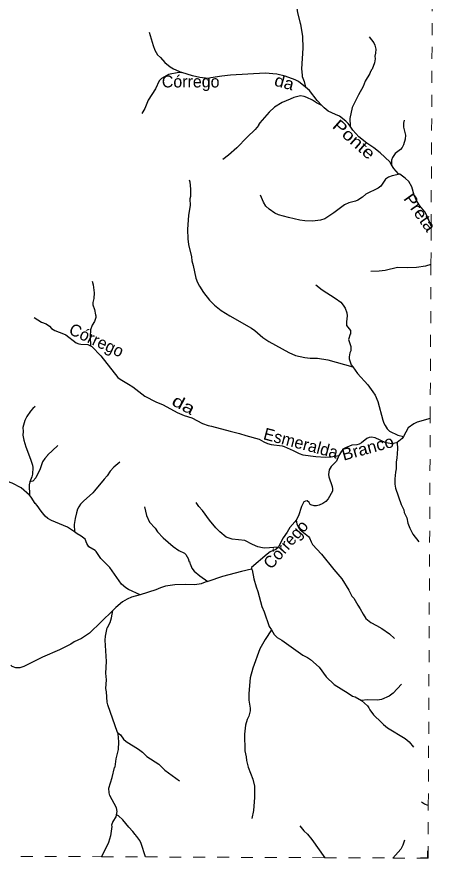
# Model space of a CAD drawing. Extents: x 551.6 to 577.6, y 7567 to 7594.7.
# Drawn here: x 573.98 to 577.56, y 7566.95 to 7573.99 of the extents above; entities that cross this region are included whole.
import ezdxf
from ezdxf.enums import TextEntityAlignment as Align

# ---------------------------------------------------------------- set-up
doc = ezdxf.new("R2010")
doc.units = 0
doc.header["$LTSCALE"] = 0.04
doc.linetypes.add('SHORT_DASHED', pattern=[2.7, 1.5, -1.2])
for name, color, linetype, lineweight in [('53', 7, 'SHORT_DASHED', 13), ('63', 7, 'Continuous', 25), ('7', 7, 'Continuous', 25)]:
    doc.layers.add(name, color=color, linetype=linetype, lineweight=lineweight)
doc.layers.add('61', color=7, linetype='Continuous')

msp = doc.modelspace()

# ---------------------------------------------------------------- linework, layer by layer
at = {"layer": '53'}
for points in [[(577.4204, 7566.9518), (577.4226, 7567.3928), (577.4384, 7570.6314), (577.4446, 7571.9213), (577.4462, 7572.242), (577.4659, 7576.2813), (577.4696, 7577.0412), (577.4755, 7578.252), (577.4832, 7579.8317), (577.4989, 7583.0336), (577.5065, 7584.6034), (577.518, 7586.9644), (577.5184, 7587.0352), (577.519, 7587.1599), (577.5202, 7587.417), (577.5286, 7589.1281), (577.5292, 7589.2596), (577.5446, 7592.4063), (577.549, 7593.3187), (577.5554, 7594.6251)], [(551.613, 7567.0572), (552.9162, 7567.0524), (553.7221, 7567.0495), (554.9107, 7567.0451), (556.1477, 7567.0406), (557.2075, 7567.0367), (559.4055, 7567.0287), (559.6981, 7567.0276), (560.556, 7567.0244), (562.9715, 7567.0156), (564.6334, 7567.0092), (566.4358, 7567.0011), (566.7714, 7566.9996), (570.8595, 7566.9812), (572.5416, 7566.9737), (572.8363, 7566.9724), (573.5039, 7566.9694), (573.609, 7566.9689), (574.6855, 7566.9641), (575.0536, 7566.9624), (576.5544, 7566.9557), (577.1266, 7566.9531), (577.4204, 7566.9518)]]:
    msp.add_lwpolyline(points, dxfattribs=at)
at = {"layer": '63'}
msp.add_lwpolyline([(577.3571, 7566.9538), (577.4187, 7566.9538), (577.4187, 7567.0145)], dxfattribs=at)
at = {"layer": '7'}
for points in [[(576.3305, 7574.5183), (576.3425, 7574.4627), (576.3441, 7574.4289), (576.3361, 7574.3388), (576.3208, 7574.2648), (576.3159, 7574.1344), (576.3208, 7574.0668), (576.3272, 7574.0265), (576.3489, 7573.9404), (576.353, 7573.9331), (576.3691, 7573.8302), (576.3723, 7573.732), (576.3594, 7573.5598), (576.365, 7573.505)], [(575.083, 7573.8664), (575.1168, 7573.7529), (575.1329, 7573.7143), (575.1554, 7573.6748), (575.1804, 7573.6539), (575.2142, 7573.6121), (575.2601, 7573.5758), (575.289, 7573.5581), (575.3583, 7573.5283)], [(576.926, 7573.8278), (576.9654, 7573.7771), (576.9743, 7573.7577), (576.9831, 7573.7231), (576.9807, 7573.6901), (576.9751, 7573.6644), (576.9767, 7573.6418), (576.9727, 7573.608), (576.9517, 7573.5573), (576.9437, 7573.5485), (576.9437, 7573.5429), (576.9373, 7573.5356), (576.9332, 7573.5211), (576.8938, 7573.4551), (576.8761, 7573.4101), (576.8366, 7573.3425), (576.7835, 7573.2346), (576.765, 7573.1445), (576.7674, 7573.0787)], [(575.3583, 7573.5283), (575.3333, 7573.5275), (575.2456, 7573.5115), (575.1868, 7573.4785), (575.1683, 7573.4584), (575.1377, 7573.3908), (575.0749, 7573.2958), (575.0476, 7573.2266), (575.0226, 7573.1855)], [(575.5997, 7573.4841), (575.5772, 7573.4793), (575.5079, 7573.4873), (575.4484, 7573.5002), (575.3583, 7573.5283)], [(576.394, 7573.4063), (576.3353, 7573.4519), (576.3063, 7573.4656), (576.2226, 7573.497), (576.155, 7573.5147), (576.0552, 7573.5227), (575.7655, 7573.505), (575.693, 7573.4986), (575.5997, 7573.4841)], [(576.365, 7573.505), (576.3666, 7573.4938), (576.3827, 7573.4535), (576.394, 7573.4063)], [(576.5304, 7573.2525), (576.4914, 7573.2926), (576.4262, 7573.3787), (576.394, 7573.4063)], [(576.5304, 7573.2525), (576.485, 7573.274), (576.4512, 7573.2966), (576.4061, 7573.3191), (576.3836, 7573.3272), (576.3514, 7573.3328), (576.295, 7573.3191), (576.2645, 7573.3038), (576.1969, 7573.2773), (576.1349, 7573.2386), (576.089, 7573.196), (576.0101, 7573.1059), (575.9988, 7573.0905), (575.9988, 7573.0857), (575.9715, 7573.0519), (575.9055, 7572.9883), (575.8178, 7572.8966), (575.7486, 7572.8362), (575.7003, 7572.7992)], [(576.6443, 7573.1767), (576.5848, 7573.2056), (576.5501, 7573.2322), (576.5304, 7573.2525)], [(576.7674, 7573.0787), (576.7522, 7573.101), (576.7328, 7573.1195), (576.6781, 7573.1614), (576.6443, 7573.1767)], [(577.2206, 7573.1292), (577.2141, 7573.1042), (577.2141, 7573.0704), (577.2302, 7573.0028), (577.2286, 7572.9706), (577.2141, 7572.9224), (577.204, 7572.901), (577.1884, 7572.8837), (577.1457, 7572.8499), (577.1224, 7572.8177), (577.1127, 7572.7936), (577.1135, 7572.7567)], [(577.1135, 7572.7567), (577.1014, 7572.7807), (577.0193, 7572.8547), (576.967, 7572.8974), (576.9075, 7572.9368), (576.8391, 7572.9884), (576.79, 7573.0455), (576.7674, 7573.0787)], [(577.1831, 7572.6774), (577.1739, 7572.6809), (577.1344, 7572.7244), (577.1135, 7572.7567)], [(577.1831, 7572.6774), (577.1192, 7572.6632), (577.0902, 7572.6535), (577.0652, 7572.635), (577.0234, 7572.5771), (577.0017, 7572.561), (576.9002, 7572.5095), (576.8721, 7572.4853), (576.8326, 7572.4588), (576.8133, 7572.4507), (576.7554, 7572.4362), (576.72, 7572.4218), (576.6306, 7572.3542), (576.5566, 7572.3043), (576.5188, 7572.293), (576.4528, 7572.2833), (576.3884, 7572.2874)], [(577.4462, 7572.242), (577.4225, 7572.3075), (577.404, 7572.3429), (577.3928, 7572.3622), (577.3525, 7572.4121), (577.3244, 7572.4572), (577.3042, 7572.5023), (577.2849, 7572.5699), (577.2584, 7572.6165), (577.2294, 7572.6447), (577.1831, 7572.6774)], [(575.4194, 7572.6286), (575.4242, 7572.6117), (575.4291, 7572.5505), (575.4291, 7572.491), (575.4258, 7572.4717), (575.4274, 7572.4153), (575.4138, 7572.3332), (575.4065, 7572.2141), (575.4081, 7572.1369), (575.4146, 7572.0886), (575.4379, 7571.984), (575.4419, 7571.9518), (575.4532, 7571.9131), (575.4765, 7571.8069), (575.4894, 7571.7699), (575.5047, 7571.7401)], [(576.3884, 7572.2874), (576.3465, 7572.293), (576.25, 7572.3139), (576.1679, 7572.3381), (576.1357, 7572.3517), (576.0882, 7572.3847), (576.0624, 7572.4105), (576.0407, 7572.4427), (576.0166, 7572.5014)], [(577.4446, 7571.9213), (577.3992, 7571.9067), (577.3236, 7571.8954), (577.2479, 7571.8922), (577.1642, 7571.897), (577.0612, 7571.8705), (577.0097, 7571.864), (576.9397, 7571.8616)], [(574.6074, 7571.7803), (574.6162, 7571.7506), (574.6226, 7571.683), (574.6194, 7571.6379), (574.6122, 7571.6041), (574.6122, 7571.5848), (574.6275, 7571.5445), (574.6339, 7571.4995), (574.6387, 7571.4922), (574.6387, 7571.4777), (574.6251, 7571.4431), (574.6065, 7571.4142), (574.5929, 7571.3755), (574.5888, 7571.3195), (574.5922, 7571.2414)], [(575.5047, 7571.7401), (575.5393, 7571.6862), (575.59, 7571.6226), (575.6319, 7571.5799), (575.6866, 7571.5373), (575.759, 7571.4914), (575.9417, 7571.3884), (575.9707, 7571.3675), (576.0367, 7571.3087), (576.0858, 7571.2757), (576.2532, 7571.1848), (576.3111, 7571.1606), (576.3498, 7571.1518)], [(576.4793, 7571.7514), (576.5333, 7571.7079), (576.6427, 7571.6395), (576.6886, 7571.6049), (576.7103, 7571.5816), (576.7248, 7571.5558), (576.7393, 7571.5172), (576.7441, 7571.4914), (576.7361, 7571.4399), (576.7361, 7571.4093), (576.7699, 7571.3691), (576.7699, 7571.3385), (576.7666, 7571.3369), (576.7538, 7571.2934), (576.7747, 7571.2355), (576.7747, 7571.1985), (576.7658, 7571.1808), (576.7618, 7571.1647), (576.7586, 7571.1486), (576.7602, 7571.1309), (576.7763, 7571.081), (576.79, 7571.0632)], [(574.1197, 7571.4761), (574.1832, 7571.4375), (574.2219, 7571.4238), (574.2492, 7571.4045), (574.2669, 7571.3852), (574.2927, 7571.3675), (574.3667, 7571.3417), (574.3861, 7571.332), (574.4738, 7571.2645), (574.4939, 7571.2564), (574.5132, 7571.2532), (574.5712, 7571.2516), (574.5922, 7571.2414)], [(574.5922, 7571.2414), (574.6041, 7571.2355), (574.6798, 7571.1558), (574.8222, 7570.9763), (574.8416, 7570.961), (574.9108, 7570.9184)], [(576.3498, 7571.1518), (576.3884, 7571.1421), (576.4335, 7571.1373), (576.493, 7571.1357), (576.5799, 7571.1228), (576.79, 7571.0632)], [(576.79, 7571.0632), (576.8294, 7571.0101), (576.9163, 7570.9152), (576.959, 7570.8556), (576.9759, 7570.8267), (577.0008, 7570.7752), (577.0427, 7570.619)], [(574.9108, 7570.9184), (574.9462, 7570.8959), (575.0484, 7570.8202), (575.1393, 7570.7727), (575.2021, 7570.747), (575.318, 7570.6826), (575.376, 7570.6576), (575.442, 7570.6383), (575.5305, 7570.5916), (575.5788, 7570.5723), (575.6077, 7570.5675), (575.7639, 7570.5273)], [(574.1301, 7570.7325), (574.1108, 7570.7164), (574.0915, 7570.6947), (574.0609, 7570.6496), (574.0432, 7570.6158), (574.0255, 7570.5562), (574.0287, 7570.5224), (574.0271, 7570.4919), (574.0335, 7570.45), (574.0512, 7570.3937), (574.0915, 7570.2923), (574.1076, 7570.2408), (574.1108, 7570.2214), (574.106, 7570.1651), (574.1011, 7570.1426), (574.0845, 7570.1017)], [(577.0427, 7570.619), (577.0507, 7570.5933), (577.0612, 7570.5723), (577.0789, 7570.545), (577.0966, 7570.5273), (577.1658, 7570.4918), (577.2141, 7570.4812)], [(577.4384, 7570.6314), (577.33, 7570.6013), (577.301, 7570.5876), (577.2544, 7570.553), (577.2141, 7570.4812)], [(575.7639, 7570.5273), (575.8411, 7570.5079), (575.8942, 7570.4902), (576.0053, 7570.4597), (576.0447, 7570.4355), (576.0761, 7570.4218), (576.1051, 7570.4146), (576.1985, 7570.4033), (576.2146, 7570.3985), (576.2902, 7570.3655), (576.3393, 7570.3389), (576.3707, 7570.3293), (576.4801, 7570.3148), (576.5622, 7570.3083), (576.6073, 7570.31), (576.6736, 7570.3213)], [(577.1626, 7570.4325), (577.1546, 7570.4274), (577.1159, 7570.4202), (577.087, 7570.4242), (577.0676, 7570.4291), (576.9759, 7570.4693), (576.9469, 7570.4749), (576.9276, 7570.4725), (576.9083, 7570.4653), (576.8616, 7570.4275), (576.8423, 7570.417), (576.823, 7570.4114), (576.7827, 7570.4098), (576.7296, 7570.3872), (576.7127, 7570.3768), (576.6942, 7570.3599), (576.6781, 7570.3309), (576.6736, 7570.3213)], [(577.1626, 7570.4325), (577.1634, 7570.3792), (577.1578, 7570.3003), (577.1521, 7570.2697), (577.1529, 7570.2118), (577.1465, 7570.1828), (577.1417, 7570.1281), (577.1425, 7570.083), (577.1481, 7570.0492), (577.1956, 7569.9124), (577.2165, 7569.8673), (577.2213, 7569.8448), (577.2415, 7569.7997), (577.2511, 7569.7547), (577.2672, 7569.7128), (577.2938, 7569.6645), (577.3437, 7569.6009)], [(577.2141, 7570.4812), (577.2028, 7570.4645), (577.1626, 7570.4325)], [(574.3193, 7570.4074), (574.2315, 7570.3245), (574.2315, 7570.3212), (574.2098, 7570.2971), (574.1905, 7570.2681), (574.172, 7570.2102), (574.1341, 7570.1353), (574.1084, 7570.1088), (574.0845, 7570.1017)], [(576.6736, 7570.3213), (576.6524, 7570.2754), (576.6097, 7570.2311), (576.5912, 7570.2021), (576.5855, 7570.1635), (576.588, 7570.1442), (576.6169, 7570.0637), (576.621, 7570.0428), (576.6185, 7570.0227), (576.5839, 7569.9599), (576.5638, 7569.9365), (576.5397, 7569.9196), (576.5091, 7569.9059), (576.4866, 7569.9011), (576.4673, 7569.9011), (576.4391, 7569.9092), (576.4318, 7569.9132), (576.4254, 7569.9277), (576.4085, 7569.943), (576.3932, 7569.9414), (576.3803, 7569.9341), (576.3594, 7569.8947), (576.3353, 7569.8174), (576.316, 7569.7824), (576.3039, 7569.7683)], [(574.8392, 7570.2673), (574.7876, 7570.2247), (574.7587, 7570.1909), (574.7321, 7570.1514), (574.7071, 7570.1249), (574.6275, 7570.0259), (574.613, 7570.0098), (574.5341, 7569.9414), (574.5092, 7569.914), (574.4955, 7569.8939), (574.4842, 7569.8722), (574.4746, 7569.8432), (574.4633, 7569.7949), (574.4569, 7569.7434), (574.4585, 7569.6847)], [(574.0817, 7569.9908), (574.0126, 7570.0508), (573.937, 7570.0902), (573.8983, 7570.1039), (573.8597, 7570.124), (573.8259, 7570.1353), (573.7723, 7570.166)], [(574.0845, 7570.1017), (574.0786, 7570.0766), (574.0817, 7569.9908)], [(574.1454, 7569.9044), (574.1333, 7569.9204), (574.1285, 7569.9212), (574.0963, 7569.9727), (574.0817, 7569.9908)], [(576.1689, 7569.5553), (576.0536, 7569.547), (576.0343, 7569.5486), (575.9957, 7569.5583), (575.9506, 7569.576), (575.8846, 7569.6106), (575.7784, 7569.6227), (575.7301, 7569.6379), (575.6753, 7569.6838), (575.6431, 7569.716), (575.5884, 7569.7804), (575.5305, 7569.8625), (575.5007, 7569.8955), (575.4766, 7569.9293)], [(574.4585, 7569.6847), (574.4005, 7569.7216), (574.2669, 7569.778), (574.2347, 7569.7949), (574.2138, 7569.8142), (574.1784, 7569.8561), (574.1454, 7569.9044)], [(575.0452, 7569.8939), (575.0605, 7569.8191), (575.0878, 7569.7643), (575.1337, 7569.7128), (575.1546, 7569.683), (575.2005, 7569.6331), (575.2842, 7569.5615), (575.3341, 7569.5285), (575.3808, 7569.5036), (575.3912, 7569.4947), (575.4146, 7569.4553), (575.4146, 7569.4472), (575.4178, 7569.444), (575.4178, 7569.436), (575.421, 7569.4352), (575.4274, 7569.4102), (575.4307, 7569.4086), (575.4427, 7569.3796), (575.4612, 7569.3547), (575.5079, 7569.3152), (575.5747, 7569.2684)], [(576.3039, 7569.7683), (576.262, 7569.7193), (576.2395, 7569.6806), (576.2057, 7569.6323), (576.1711, 7569.5647), (576.1689, 7569.5553)], [(576.316, 7569.7824), (576.3224, 7569.7498), (576.3353, 7569.7209), (576.3497, 7569.6991), (576.4198, 7569.6452), (576.4286, 7569.6339), (576.4399, 7569.6001), (576.4512, 7569.5784), (576.5276, 7569.4963), (576.6298, 7569.3675), (576.6982, 7569.2911), (576.7562, 7569.1961), (576.7827, 7569.1446), (576.7972, 7569.1269), (576.831, 7569.0682), (576.8527, 7569.04), (576.8769, 7568.9933), (576.8994, 7568.9587), (576.9413, 7568.9257), (576.9888, 7568.8983)], [(575.0076, 7569.1551), (574.9108, 7569.2001), (574.8882, 7569.2146), (574.8536, 7569.2444), (574.7554, 7569.3836), (574.6806, 7569.4601), (574.6621, 7569.4843), (574.6412, 7569.5196), (574.6323, 7569.5285), (574.5776, 7569.5575), (574.5615, 7569.5857), (574.5478, 7569.6211), (574.5148, 7569.6468), (574.481, 7569.6661), (574.4585, 7569.6847)], [(576.1689, 7569.5553), (576.1453, 7569.5357), (576.0971, 7569.5148), (576.0721, 7569.4971), (575.9414, 7569.3842), (575.9414, 7569.371)], [(575.9414, 7569.371), (575.8588, 7569.3522), (575.6979, 7569.3088), (575.5747, 7569.2684), (575.553, 7569.2613)], [(575.9414, 7569.371), (575.9457, 7569.3651), (575.9602, 7569.2911), (575.9795, 7569.2219), (575.994, 7569.1833), (576.0286, 7569.0593), (576.0488, 7569.0143), (576.089, 7568.8919), (576.1079, 7568.862)], [(575.553, 7569.2613), (575.5208, 7569.2492), (575.4661, 7569.2388), (575.3888, 7569.2412), (575.2987, 7569.2396), (575.2198, 7569.2283), (575.1796, 7569.2154), (575.141, 7569.1985), (575.0076, 7569.1551)], [(575.0076, 7569.1551), (574.9365, 7569.1366), (574.8987, 7569.1205), (574.8609, 7569.0971), (574.8053, 7569.0513), (574.779, 7569.0239)], [(574.779, 7569.0239), (574.5856, 7568.8356), (574.5164, 7568.7905)], [(574.7579, 7568.9241), (574.7691, 7568.9627), (574.779, 7569.0239)], [(574.8195, 7568.0051), (574.7369, 7568.2352), (574.7313, 7568.2577), (574.7273, 7568.343), (574.7224, 7568.372), (574.7257, 7568.4445), (574.7208, 7568.5008), (574.7257, 7568.599), (574.7144, 7568.776), (574.7176, 7568.8098), (574.732, 7568.8804), (574.7353, 7568.8814), (574.7579, 7568.9241)], [(576.9888, 7568.8983), (577.0338, 7568.8734), (577.0982, 7568.8291), (577.1393, 7568.7897)], [(576.1079, 7568.862), (576.0552, 7568.7825), (576.0117, 7568.7036), (575.9538, 7568.541), (575.9296, 7568.4622), (575.9184, 7568.3302), (575.92, 7568.2754), (575.9296, 7568.2078), (575.9296, 7568.1853), (575.9192, 7568.1418), (575.9055, 7568.1129), (575.891, 7568.0646), (575.8814, 7567.9889), (575.8862, 7567.8489), (575.8974, 7567.8006)], [(576.1079, 7568.862), (576.1317, 7568.8243), (576.1558, 7568.7985), (576.1944, 7568.776), (576.3723, 7568.6513), (576.4093, 7568.6328), (576.4343, 7568.6159), (576.5091, 7568.5507), (576.5662, 7568.4694), (576.6331, 7568.4042), (576.7514, 7568.3334)], [(574.5164, 7568.7905), (574.4569, 7568.7623), (574.4279, 7568.7438), (574.3329, 7568.6947), (574.1913, 7568.6352), (574.0352, 7568.5571), (574.0014, 7568.5458), (573.9676, 7568.5458), (573.937, 7568.5571), (573.9257, 7568.5682)], [(577.1988, 7568.4082), (577.1288, 7568.3326), (577.0934, 7568.3084), (577.0306, 7568.2795), (576.9968, 7568.273), (576.9099, 7568.277), (576.8626, 7568.2702)], [(576.7514, 7568.3334), (576.7876, 7568.3092), (576.809, 7568.3014), (576.8626, 7568.2702)], [(576.8626, 7568.2702), (576.9139, 7568.2263), (576.9244, 7568.2111), (576.9316, 7568.1925), (576.9622, 7568.1523), (577.0314, 7568.0887), (577.0483, 7568.0694), (577.0813, 7568.042), (577.2286, 7567.9535), (577.2616, 7567.9246), (577.2978, 7567.8803)], [(574.8112, 7567.3158), (574.8149, 7567.3411), (574.8094, 7567.3741), (574.7546, 7567.4755), (574.7498, 7567.498), (574.7474, 7567.5382), (574.7731, 7567.6284), (574.7925, 7567.7121), (574.7981, 7567.7161), (574.8077, 7567.7845), (574.8287, 7567.8618), (574.8303, 7567.9262), (574.8271, 7567.96)], [(574.8271, 7567.96), (574.8238, 7567.993), (574.8195, 7568.0051)], [(574.8195, 7568.0051), (574.8448, 7567.9833), (574.8689, 7567.9487), (574.8907, 7567.9294), (574.9961, 7567.8642), (575.0291, 7567.8384), (575.0645, 7567.803), (575.1651, 7567.7378), (575.215, 7567.6895), (575.3381, 7567.5994)], [(575.8974, 7567.8006), (575.9007, 7567.77), (575.9143, 7567.7137), (575.9522, 7567.6123), (575.9659, 7567.5543), (575.9675, 7567.461), (575.957, 7567.3499), (575.9441, 7567.2831)], [(577.4226, 7567.3928), (577.3912, 7567.4046), (577.3662, 7567.4199)], [(574.8112, 7567.3158), (574.8061, 7567.2984), (574.7796, 7567.2598), (574.7691, 7567.2276), (574.7707, 7567.2163), (574.7611, 7567.1375), (574.7442, 7567.0827), (574.6855, 7566.9641)], [(575.0536, 7566.9624), (575.017, 7567.0747), (575.0049, 7567.1004), (574.9816, 7567.1334), (574.9767, 7567.1358), (574.9735, 7567.1439), (574.9663, 7567.1487), (574.947, 7567.1761), (574.9132, 7567.2123), (574.8641, 7567.2727), (574.8271, 7567.3072), (574.8112, 7567.3158)], [(576.3457, 7567.222), (576.3803, 7567.1809), (576.4109, 7567.1519), (576.4463, 7567.1069), (576.5544, 7566.9557)], [(577.2222, 7567.1028), (577.2093, 7567.0618), (577.1916, 7567.028), (577.1266, 7566.9531)]]:
    msp.add_lwpolyline(points, dxfattribs=at)

# ---------------------------------------------------------------- texts
at = {"layer": '61'}
msp.add_text('Córrego', height=0.1, dxfattribs=at).set_placement((575.4317, 7573.4032), align=Align.CENTER)
for s, rotation, width, p in [('da', 344.721, 1.1, (576.2039, 7573.3987)), ('Ponte', 318.376, 1.2, (576.7671, 7572.9313)), ('Preta', 305.281, 1.1, (577.3112, 7572.3286)), ('da', 332.074, 1.3, (575.3498, 7570.7043)), ('Branco', 15.506, 1.05, (576.9275, 7570.3379))]:
    msp.add_text(s, height=0.1, rotation=rotation, dxfattribs=dict(at, width=width)).set_placement(p, align=Align.CENTER)
for s, rotation, p in [('Córrego', 335.221, (574.6223, 7571.2425)), ('Esmeralda', 345.169, (576.3428, 7570.3777)), ('Córrego', 48.671, (576.2656, 7569.5447))]:
    msp.add_text(s, height=0.1, rotation=rotation, dxfattribs=at).set_placement(p, align=Align.CENTER)

doc.saveas('drawing.dxf')
